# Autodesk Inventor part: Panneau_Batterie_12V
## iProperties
Created: 2010-11
Part Number: Panneau_Batterie_12V
Document SubType Name: Modeling
Designer: Alex_Cyril
Author: Alex_Cyril
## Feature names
1. Extrusion1
2. Extrusion2
3. Extrusion3
4. Extrusion4
